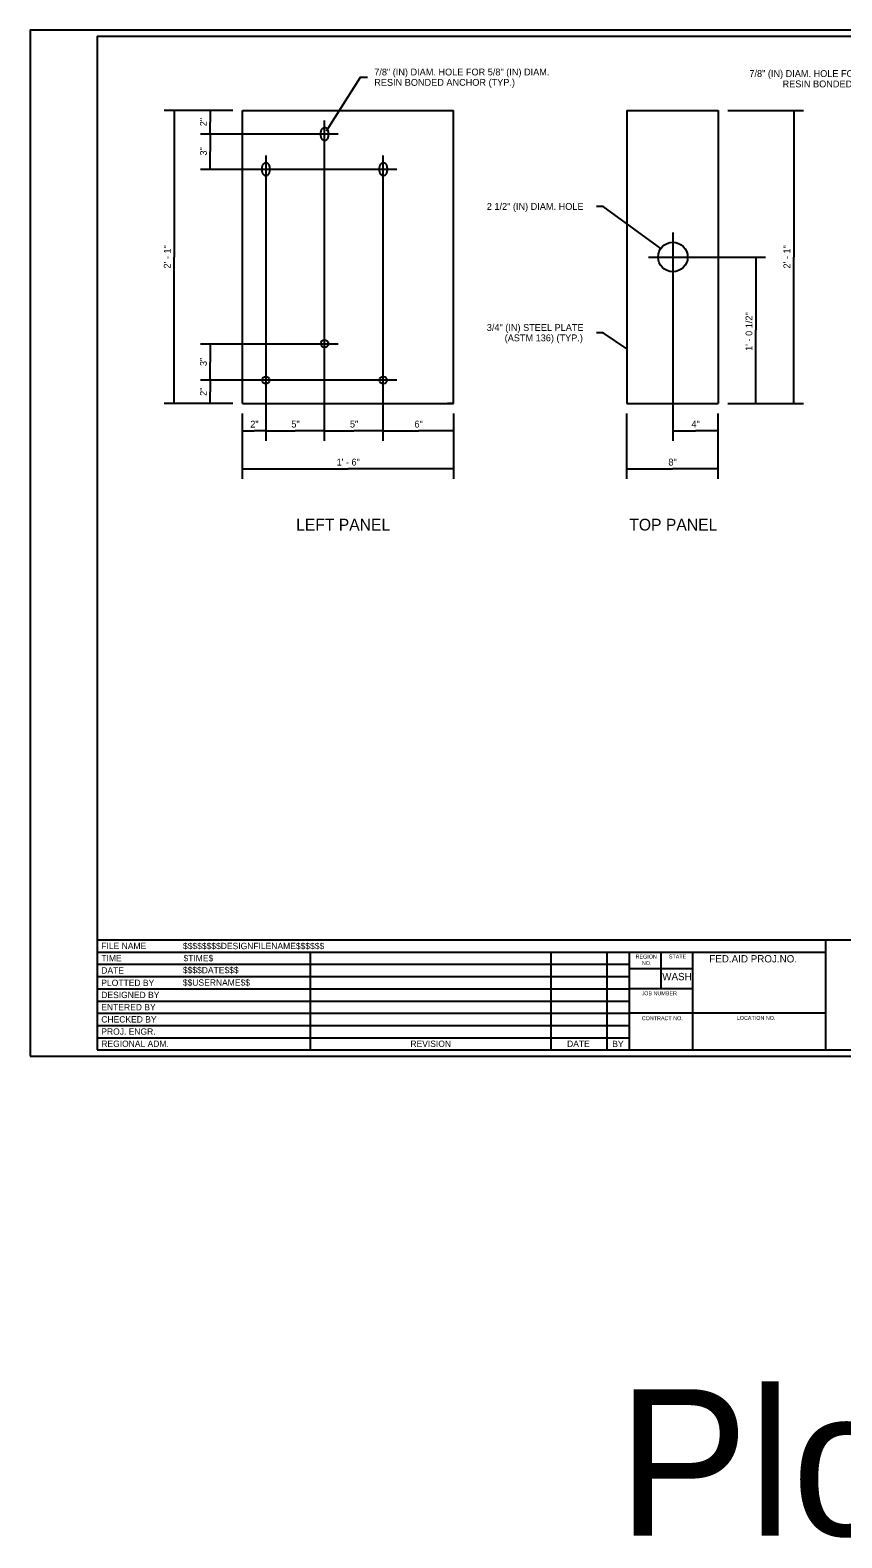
# Model space of a CAD drawing. Extents: x 99988 to 100172, y 99995 to 100047.
# Drawn here: x 100019.31 to 100027.62, y 99995.01 to 100010.44 of the extents above; entities that cross this region are included whole.
import ezdxf

# ---------------------------------------------------------------- set-up
doc = ezdxf.new("R2010")
doc.units = 0
for name, color, linetype in [('Level 10', 7, 'Continuous'), ('Level 12', 7, 'Continuous'), ('Level 15', 7, 'Continuous'), ('Level 19', 7, 'Continuous'), ('Level 20', 7, 'Continuous'), ('SH_GI_PlotLimits', 7, 'Continuous'), ('SH_GI_SheetBorder', 7, 'Continuous'), ('SH_GI_SheetLocationText', 7, 'Continuous'), ('SH_GI_SheetTextInCells', 7, 'Continuous'), ('SH_GI_TitleBlockText', 7, 'Continuous')]:
    doc.layers.add(name, color=color, linetype=linetype)

msp = doc.modelspace()

# ---------------------------------------------------------------- linework, layer by layer
at = {"layer": 'Level 10'}
for points in [[(100022.364, 100009.374), (100022.364, 100009.451), (100022.287, 100009.451), (100022.287, 100009.374), (100022.287, 100009.296), (100022.364, 100009.296), (100022.364, 100009.374)], [(100021.763, 100009.014), (100021.763, 100009.092), (100021.686, 100009.092), (100021.686, 100009.014), (100021.686, 100008.937), (100021.763, 100008.937), (100021.763, 100009.014)], [(100022.966, 100009.014), (100022.966, 100009.092), (100022.888, 100009.092), (100022.888, 100009.014), (100022.888, 100008.937), (100022.966, 100008.937), (100022.966, 100009.014)]]:
    msp.add_open_spline(points, degree=4, dxfattribs=at)
at = {"layer": 'Level 12'}
for p, q in [((100021.486, 100006.615), (100021.487, 100009.615)), ((100021.487, 100009.615), (100021.487, 100009.615)), ((100023.647, 100006.615), (100023.647, 100009.615)), ((100025.42, 100009.615), (100025.42, 100006.615)), ((100025.42, 100009.615), (100026.354, 100009.615)), ((100026.354, 100009.615), (100026.354, 100006.615)), ((100023.647, 100006.615), (100023.586, 100006.615)), ((100025.42, 100006.615), (100026.354, 100006.615))]:
    msp.add_line(p, q, dxfattribs=at)
for points in [[(100021.487, 100009.615), (100023.647, 100009.615)], [(100021.486, 100006.615), (100023.647, 100006.615)]]:
    msp.add_lwpolyline(points, dxfattribs=at)
msp.add_circle((100025.892, 100008.115), 0.151, dxfattribs=at)
at = {"layer": 'Level 15'}
for p, q in [((100021.387, 100009.615), (100020.686, 100009.615)), ((100020.786, 100009.615), (100020.786, 100008.115)), ((100021.156, 100009.615), (100021.156, 100009.495)), ((100026.454, 100009.615), (100027.229, 100009.615)), ((100027.129, 100009.615), (100027.129, 100008.115)), ((100021.056, 100009.375), (100022.464, 100009.375)), ((100021.156, 100009.375), (100021.156, 100009.495)), ((100021.156, 100009.375), (100021.156, 100009.195)), ((100022.327, 100006.235), (100022.327, 100009.512)), ((100021.156, 100009.015), (100021.156, 100009.195)), ((100021.727, 100006.235), (100021.727, 100009.153)), ((100022.927, 100006.235), (100022.927, 100009.153)), ((100021.056, 100009.015), (100023.066, 100009.015)), ((100025.892, 100008.366), (100025.892, 100006.235)), ((100020.786, 100006.615), (100020.786, 100008.115)), ((100025.641, 100008.115), (100026.841, 100008.115)), ((100026.741, 100008.115), (100026.741, 100007.365)), ((100027.129, 100006.615), (100027.129, 100008.115)), ((100026.741, 100006.615), (100026.741, 100007.365)), ((100022.464, 100007.225), (100021.056, 100007.225)), ((100021.156, 100007.225), (100021.156, 100007.04)), ((100021.156, 100006.855), (100021.156, 100007.04)), ((100023.066, 100006.855), (100021.056, 100006.855)), ((100021.156, 100006.855), (100021.156, 100006.735)), ((100021.386, 100006.615), (100020.686, 100006.615)), ((100021.156, 100006.615), (100021.156, 100006.735)), ((100026.454, 100006.615), (100027.229, 100006.615)), ((100021.486, 100005.846), (100021.486, 100006.515)), ((100023.647, 100006.515), (100023.647, 100005.846)), ((100025.42, 100005.846), (100025.42, 100006.515)), ((100026.354, 100005.846), (100026.354, 100006.515)), ((100021.486, 100006.335), (100021.607, 100006.335)), ((100021.727, 100006.335), (100021.607, 100006.335)), ((100021.727, 100006.335), (100022.027, 100006.335)), ((100022.327, 100006.335), (100022.027, 100006.335)), ((100022.327, 100006.335), (100022.627, 100006.335)), ((100022.927, 100006.335), (100022.627, 100006.335)), ((100022.927, 100006.335), (100023.287, 100006.335)), ((100023.647, 100006.335), (100023.287, 100006.335)), ((100025.892, 100006.335), (100026.123, 100006.335)), ((100026.354, 100006.335), (100026.123, 100006.335)), ((100021.486, 100005.946), (100022.567, 100005.946)), ((100023.647, 100005.946), (100022.567, 100005.946)), ((100025.42, 100005.946), (100025.887, 100005.946)), ((100026.354, 100005.946), (100025.887, 100005.946))]:
    msp.add_line(p, q, dxfattribs=at)
for points in [[(100022.346, 100009.406), (100022.695, 100009.956), (100022.765, 100009.956)], [(100025.77, 100008.204), (100025.18, 100008.633), (100025.11, 100008.633)], [(100025.42, 100007.174), (100025.18, 100007.341), (100025.11, 100007.341)]]:
    msp.add_lwpolyline(points, dxfattribs=at)
at = {"layer": 'Level 19'}
for centre in [(100022.326, 100007.229), (100021.725, 100006.855), (100022.927, 100006.855)]:
    msp.add_ellipse(centre, major_axis=(0, -0.0386), ratio=0.999999, dxfattribs=at)
at = {"layer": 'SH_GI_PlotLimits'}
msp.add_lwpolyline([(100019.312, 99999.937), (100035.812, 99999.937), (100035.812, 100010.437), (100019.312, 100010.437)], close=True, dxfattribs=at)
at = {"layer": 'SH_GI_SheetBorder'}
for p, q in [((100020, 100010.375), (100020, 100000)), ((100020, 100010.375), (100035.75, 100010.375)), ((100020, 100001.126), (100035.75, 100001.126)), ((100027.457, 100000), (100027.457, 100001.126)), ((100020, 100001.001), (100027.457, 100001.001)), ((100022.179, 100001.001), (100022.179, 100000)), ((100024.641, 100001.001), (100024.641, 100000)), ((100025.216, 100001.001), (100025.216, 100000)), ((100025.445, 100001.001), (100025.445, 100000)), ((100025.772, 100000.625), (100025.772, 100001.001)), ((100026.096, 100000), (100026.096, 100001.001)), ((100020, 100000.876), (100022.182, 100000.876)), ((100020, 100000.751), (100022.182, 100000.751)), ((100022.182, 100000.876), (100025.447, 100000.876)), ((100022.182, 100000.751), (100025.447, 100000.751)), ((100026.096, 100000.831), (100025.447, 100000.831)), ((100020, 100000.625), (100025.447, 100000.625)), ((100026.096, 100000.625), (100025.447, 100000.625)), ((100020, 100000.5), (100025.447, 100000.5)), ((100020, 100000.375), (100025.447, 100000.375)), ((100027.457, 100000.375), (100025.447, 100000.375)), ((100020, 100000.25), (100025.447, 100000.25)), ((100020, 100000.125), (100025.447, 100000.125)), ((100020, 100000), (100035.75, 100000))]:
    msp.add_line(p, q, dxfattribs=at)

# ---------------------------------------------------------------- texts
at = {"layer": 'Level 20'}
for s, rotation, p in [('7/8" (IN) DIAM. HOLE FOR 5/8" (IN) DIAM.', 360, (100022.835, 100009.974)), ('RESIN BONDED ANCHOR (TYP.)', 360, (100022.835, 100009.868)), ('2"', 90, (100021.121, 100009.454)), ('3"', 90, (100021.121, 100009.154)), ('2\' - 1"', 90, (100020.751, 100007.998)), ('2\' - 1"', 90, (100027.094, 100007.998)), ('1\' - 0 1/2"', 90, (100026.706, 100007.155)), ('3"', 90, (100021.121, 100006.999)), ('2"', 90, (100021.121, 100006.694))]:
    msp.add_text(s, height=0.07, rotation=rotation, dxfattribs=at).set_placement(p)
for s, height, p in [('7/8" (IN) DIAM. HOLE FOR 5/8" (IN) DIAM.', 0.07, (100026.675, 100009.958)), ('RESIN BONDED ANCHOR (TYP.)', 0.07, (100027.015, 100009.852)), ('2 1/2" (IN) DIAM. HOLE', 0.07, (100023.987, 100008.598)), ('3/4" (IN) STEEL PLATE', 0.07, (100023.987, 100007.359)), ('(ASTM 136) (TYP.)', 0.07, (100024.17, 100007.253)), ('2"', 0.07, (100021.566, 100006.37)), ('5"', 0.07, (100021.986, 100006.37)), ('5"', 0.07, (100022.586, 100006.37)), ('6"', 0.07, (100023.246, 100006.37)), ('4"', 0.07, (100026.082, 100006.37)), ('1\' - 6"', 0.07, (100022.449, 100005.981)), ('8"', 0.07, (100025.846, 100005.981)), ('LEFT PANEL', 0.12, (100022.035, 100005.316)), ('TOP PANEL', 0.12, (100025.446, 100005.316))]:
    msp.add_text(s, height=height, dxfattribs=at).set_placement(p)
at = {"layer": 'SH_GI_SheetLocationText'}
msp.add_text('Plot 2', height=1.5, dxfattribs=at).set_placement((100025.327, 99995.027))
at = {"layer": 'SH_GI_SheetTextInCells'}
for s, height, p in [('FILE NAME', 0.0651, (100020.041, 100001.031)), ('TIME', 0.0651, (100020.041, 100000.906)), ('REGION', 0.04, (100025.51, 100000.935)), ('NO.', 0.04, (100025.575, 100000.869)), ('STATE', 0.04, (100025.851, 100000.936)), ('FED.AID PROJ.NO.', 0.07506, (100026.265, 100000.895)), ('DATE', 0.0651, (100020.041, 100000.781)), ('WASH', 0.0751, (100025.783, 100000.713)), ('PLOTTED BY', 0.0651, (100020.041, 100000.654)), ('DESIGNED BY', 0.06505, (100020.041, 100000.53)), ('JOB NUMBER', 0.04, (100025.571, 100000.559)), ('ENTERED BY', 0.0651, (100020.041, 100000.405)), ('CHECKED BY', 0.0651, (100020.041, 100000.28)), ('CONTRACT NO.', 0.04003, (100025.573, 100000.304)), ('LOCATION NO.', 0.04003, (100026.546, 100000.307)), ('PROJ. ENGR.', 0.06505, (100020.041, 100000.155)), ('REGIONAL ADM.', 0.06505, (100020.041, 100000.03)), ('REVISION', 0.0651, (100023.205, 100000.03)), ('DATE', 0.0651, (100024.809, 100000.03)), ('BY', 0.0651, (100025.272, 100000.028))]:
    msp.add_text(s, height=height, dxfattribs=at).set_placement(p)
at = {"layer": 'SH_GI_TitleBlockText'}
for s, height, p in [('$$$$$$$$DESIGNFILENAME$$$$$$', 0.06505, (100020.877, 100001.031)), ('$TIME$', 0.0651, (100020.882, 100000.906)), ('$$$$DATE$$$', 0.06505, (100020.876, 100000.784)), ('$$USERNAME$$', 0.06505, (100020.876, 100000.657))]:
    msp.add_text(s, height=height, dxfattribs=at).set_placement(p)

doc.saveas('drawing.dxf')
